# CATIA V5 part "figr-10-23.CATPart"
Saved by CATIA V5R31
Part number: Part1
Bounding box of the stored display mesh (mm): x -174.518 to 0, y -36.805 to 36.805, z 0 to 36.805
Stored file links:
  D:\PROJECTS\Project 2021\US EDITION\CATIA V5 6R 2021\Resources\Part Files\c10_catia_v5_6r2021_prt\c10_catia_v5_6r2021_prt\figr-10-23.CATPart
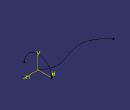
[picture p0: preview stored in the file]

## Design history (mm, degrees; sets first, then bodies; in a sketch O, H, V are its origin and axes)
Body1 (main body)
  Sketch1 on xy-plane, origin (0, 0, 0), H (1, 0, 0), V (0, 1, 0)
    spline S1 through (0, 0) (-31.5913, 14.7273) (-94.8038, 0) (-174.5181, 29.5113)
    point P1 (0, 0)
    point P2 (-94.8038, 0)
    coincidence: P1 O, P2 H
  Sketch2 on yz-plane, origin (0, 0, 0), H (0, 1, 0), V (0, 0, 1)
    arc A1 centre (0, 0) radius 36.8048 from (36.8048, 0) to (-36.8048, 0) ccw
    point P1 (-36.8048, 0)
    point P2 (36.8048, 0)
    coincidence: P1 H, P2 H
